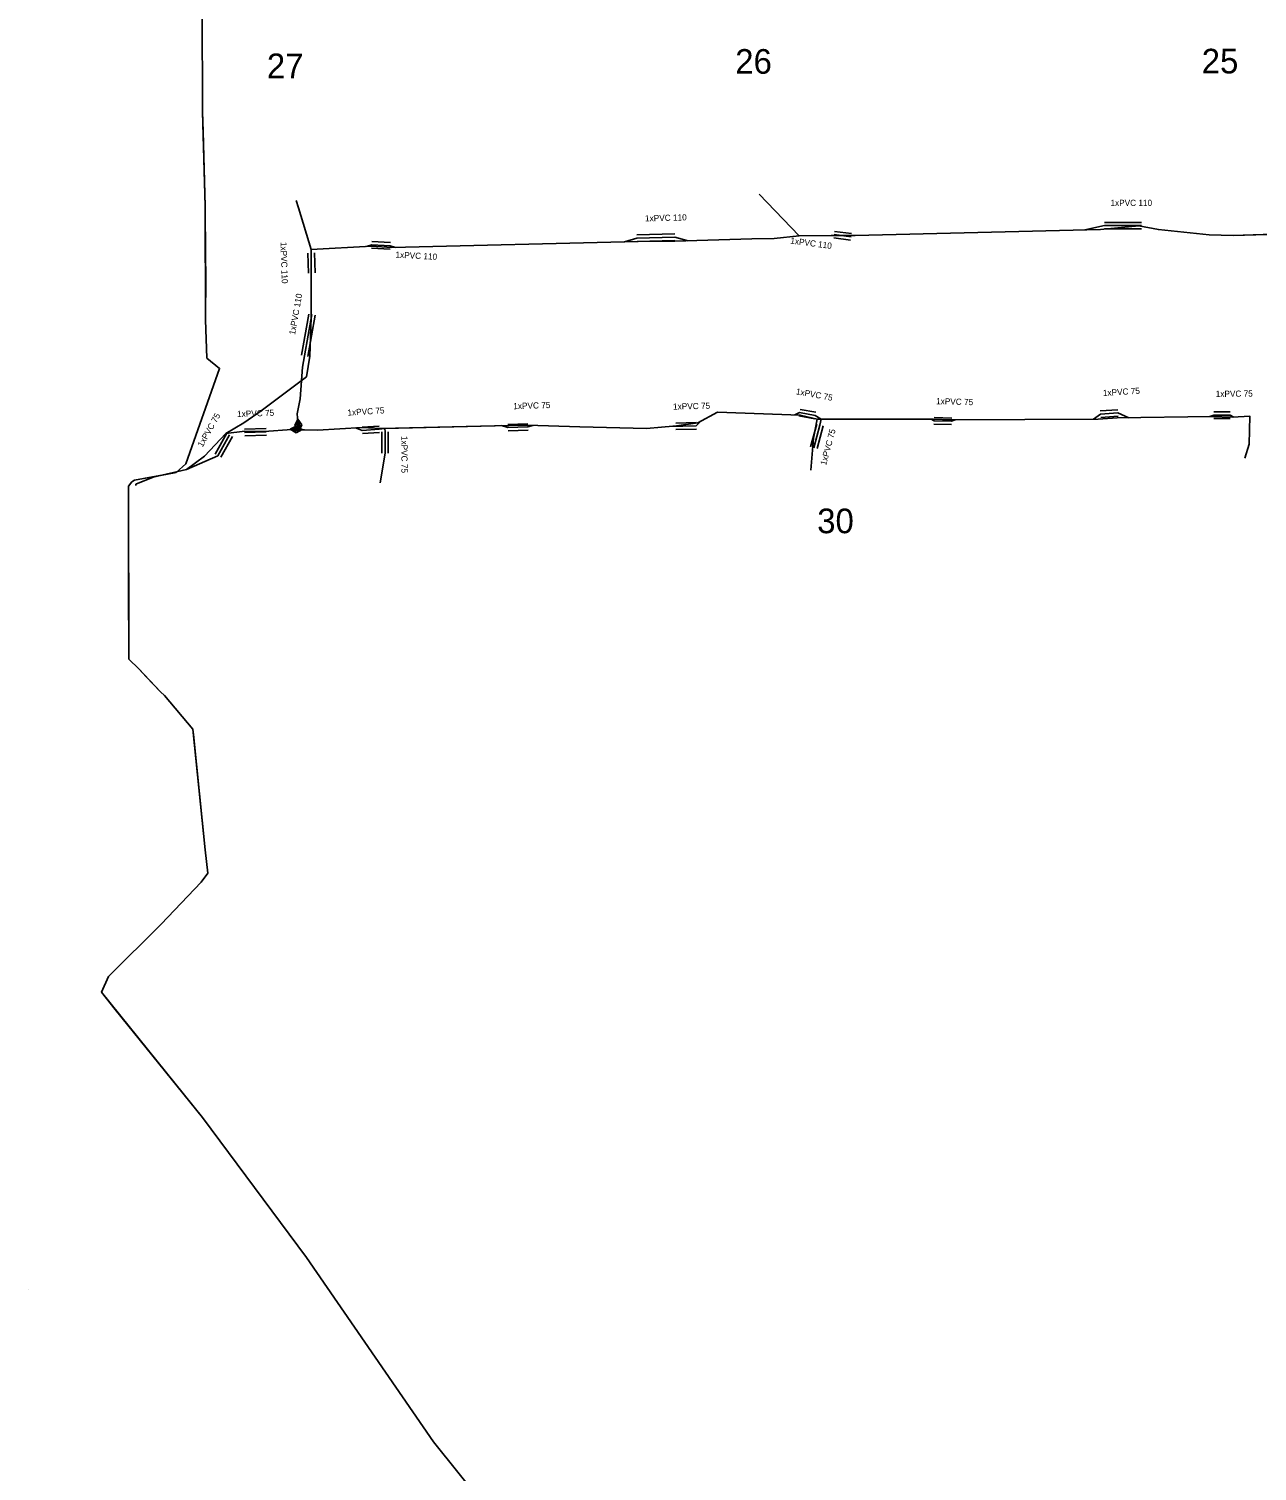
# Model space of a CAD drawing. Extents: x -651943 to -618711, y -1138561 to -1100552.
# Drawn here: x -641572.3 to -641422.8, y -1115022.1 to -1114846.4 of the extents above; entities that cross this region are included whole.
import ezdxf

# ---------------------------------------------------------------- set-up
doc = ezdxf.new("R2010")
doc.units = 0
for name, color, linetype in [('KT optika', 7, 'Continuous'), ('KT trasa', 7, 'Continuous'), ('KT zařízení', 7, 'Continuous'), ('SATT bloky', 7, 'Continuous'), ('SATT stanice', 7, 'Continuous')]:
    doc.layers.add(name, color=color, linetype=linetype)

# ---------------------------------------------------------------- blocks, each defined once
blk = doc.blocks.new('POINT_DISPLAY')
blk.add_line((0, 0), (0, 0))
blk = doc.blocks.new('TVSPO_1')
at = {"layer": 'KT zařízení'}
for p, q in [((-0.074, 0.002), (0, 0.044)), ((-0.001, -0.041), (-0.074, 0.002)), ((-0.035, 0), (0, 0.02)), ((0.073, 0.001), (-0.001, -0.041)), ((0, 0.044), (0.073, 0.001)), ((0, 0.02), (0.035, 0)), ((0.035, 0), (0, -0.02)), ((0, -0.02), (-0.035, 0))]:
    blk.add_line(p, q, dxfattribs=at)

msp = doc.modelspace()

# ---------------------------------------------------------------- linework, layer by layer
at = {"layer": 'KT optika'}
for points in [[(-641551.21, -1114844.02), (-641551.16, -1114856.5), (-641550.86, -1114868.02), (-641550.82, -1114881.85), (-641550.66, -1114886.51), (-641549.1, -1114887.77), (-641553.22, -1114899.39), (-641554.4, -1114900.46), (-641557.15, -1114900.97)], [(-641478.52, -1114871.61), (-641478.52, -1114871.61), (-641483.41, -1114866.54)], [(-641537.95, -1114873.29), (-641539.48, -1114868.22), (-641539.75, -1114867.3)], [(-641537.95, -1114873.29), (-641530.6, -1114872.9), (-641528.11, -1114873.06), (-641498.14, -1114872.31), (-641493.68, -1114872.28), (-641484.29, -1114871.98), (-641481.55, -1114871.94), (-641478.52, -1114871.61)], [(-641478.52, -1114871.61), (-641474.62, -1114871.59), (-641471.72, -1114871.6), (-641441.85, -1114870.85), (-641437.18, -1114870.41), (-641434.79, -1114870.87), (-641428.62, -1114871.49), (-641425.7, -1114871.59), (-641418.41, -1114871.36)], [(-641537.95, -1114873.29), (-641537.93, -1114879.08), (-641537.93, -1114881.58), (-641538.12, -1114886.28), (-641538.53, -1114888.79), (-641544.03, -1114892.94), (-641546.16, -1114894.4), (-641548.32, -1114895.69)], [(-641539.47, -1114895.24), (-641539.47, -1114895.24), (-641539.64, -1114893.32), (-641539.29, -1114891.49), (-641539, -1114887.63), (-641538.74, -1114886.24), (-641537.85, -1114881.22)], [(-641528.96, -1114895.08), (-641513.86, -1114894.72), (-641511.59, -1114894.69), (-641505.25, -1114894.88), (-641497.11, -1114895.09), (-641493.47, -1114894.78), (-641490.86, -1114894.4), (-641488.47, -1114893.09), (-641478.39, -1114893.45), (-641476.35, -1114893.94)], [(-641539.47, -1114895.24), (-641537.16, -1114895.31), (-641531.72, -1114894.98), (-641529.4, -1114895.09), (-641528.96, -1114895.08)], [(-641476.35, -1114893.94), (-641476.35, -1114893.94), (-641476.79, -1114896.27), (-641477.09, -1114900.15)], [(-641476.35, -1114893.94), (-641462.16, -1114893.97), (-641459.98, -1114894.05), (-641442.12, -1114893.94), (-641439.82, -1114893.8), (-641428.31, -1114893.64), (-641425.78, -1114893.7), (-641423.65, -1114893.61), (-641423.73, -1114897.02), (-641424.25, -1114898.7)], [(-641548.32, -1114895.69), (-641548.32, -1114895.69), (-641550.94, -1114898.46), (-641553.11, -1114900.1), (-641557.19, -1114901.02)], [(-641548.32, -1114895.69), (-641546.03, -1114895.41), (-641543.65, -1114895.44), (-641540.28, -1114895.22), (-641539.47, -1114895.24)], [(-641528.96, -1114895.08), (-641528.95, -1114895.49), (-641528.95, -1114898.1), (-641529.53, -1114901.7)], [(-641557.26, -1114900.99), (-641559.44, -1114901.39), (-641559.79, -1114901.6), (-641560.19, -1114902.13), (-641560.15, -1114923.19), (-641558.93, -1114924.36), (-641556.3, -1114927.18), (-641555.82, -1114927.61), (-641552.35, -1114931.72), (-641550.85, -1114946.43), (-641550.52, -1114949.25), (-641551.32, -1114950.36), (-641556.21, -1114955.48), (-641562.63, -1114961.85), (-641563.46, -1114963.76), (-641551.19, -1114979.03), (-641538.52, -1114996.06), (-641523.04, -1115018.52), (-641502.48, -1115044.21)]]:
    msp.add_lwpolyline(points, dxfattribs=at)
at = {"layer": 'KT trasa'}
for p, q in [((-641551.21, -1114844.02), (-641551.16, -1114856.5)), ((-641551.16, -1114856.5), (-641551.11, -1114858.93)), ((-641551.11, -1114858.93), (-641550.86, -1114868.02)), ((-641478.52, -1114871.61), (-641483.41, -1114866.54)), ((-641550.86, -1114868.02), (-641550.79, -1114874.2)), ((-641539.48, -1114868.22), (-641539.75, -1114867.3)), ((-641537.95, -1114873.29), (-641539.48, -1114868.22)), ((-641441.33, -1114870.38), (-641443.76, -1114870.9)), ((-641436.86, -1114870.38), (-641441.33, -1114870.38)), ((-641498.27, -1114871.9), (-641499.78, -1114872.35)), ((-641493.66, -1114871.78), (-641498.27, -1114871.9)), ((-641484.29, -1114871.98), (-641493.68, -1114872.28)), ((-641493.66, -1114871.78), (-641492.04, -1114872.23)), ((-641481.55, -1114871.94), (-641484.29, -1114871.98)), ((-641478.52, -1114871.61), (-641481.55, -1114871.94)), ((-641474.62, -1114871.59), (-641478.52, -1114871.61)), ((-641471.72, -1114871.6), (-641474.62, -1114871.59)), ((-641472.21, -1114871.75), (-641474.26, -1114871.48)), ((-641441.85, -1114870.85), (-641471.72, -1114871.6)), ((-641437.18, -1114870.41), (-641441.85, -1114870.85)), ((-641434.79, -1114870.87), (-641437.18, -1114870.41)), ((-641428.62, -1114871.49), (-641434.79, -1114870.87)), ((-641425.7, -1114871.59), (-641428.62, -1114871.49)), ((-641418.41, -1114871.36), (-641425.7, -1114871.59)), ((-641530.6, -1114872.9), (-641537.95, -1114873.29)), ((-641537.95, -1114873.29), (-641537.93, -1114879.08)), ((-641530.56, -1114872.71), (-641531.2, -1114872.93)), ((-641528.11, -1114873.06), (-641530.6, -1114872.9)), ((-641528.32, -1114872.83), (-641530.56, -1114872.71)), ((-641528.32, -1114872.83), (-641527.68, -1114873.05)), ((-641498.14, -1114872.31), (-641528.11, -1114873.06)), ((-641493.68, -1114872.28), (-641498.14, -1114872.31)), ((-641550.79, -1114874.2), (-641550.78, -1114876.49)), ((-641550.78, -1114876.49), (-641550.82, -1114881.85)), ((-641537.93, -1114879.08), (-641537.93, -1114881.58)), ((-641550.82, -1114881.85), (-641550.66, -1114886.51)), ((-641537.93, -1114881.58), (-641538.12, -1114886.28)), ((-641553.22, -1114899.39), (-641549.1, -1114887.77)), ((-641550.66, -1114886.51), (-641549.1, -1114887.77)), ((-641539, -1114887.63), (-641539.29, -1114891.49)), ((-641538.74, -1114886.24), (-641539, -1114887.63)), ((-641538.12, -1114886.28), (-641538.53, -1114888.79)), ((-641538.53, -1114888.79), (-641544.03, -1114892.94)), ((-641539.29, -1114891.49), (-641539.64, -1114893.32)), ((-641544.03, -1114892.94), (-641546.16, -1114894.4)), ((-641490.86, -1114894.4), (-641488.47, -1114893.09)), ((-641488.47, -1114893.09), (-641478.39, -1114893.45)), ((-641478.48, -1114893.16), (-641479.06, -1114893.42)), ((-641478.48, -1114893.16), (-641476.56, -1114893.51)), ((-641439.71, -1114893.2), (-641441.83, -1114893.34)), ((-641438.37, -1114893.78), (-641439.71, -1114893.2)), ((-641546.16, -1114894.4), (-641548.32, -1114895.69)), ((-641539.64, -1114893.32), (-641539.47, -1114895.24)), ((-641537.16, -1114895.31), (-641531.72, -1114894.98)), ((-641531.72, -1114894.98), (-641529.4, -1114895.09)), ((-641529.4, -1114895.09), (-641513.86, -1114894.72)), ((-641513.98, -1114894.99), (-641514.75, -1114894.74)), ((-641513.98, -1114894.99), (-641511.55, -1114894.91)), ((-641513.86, -1114894.72), (-641511.59, -1114894.69)), ((-641511.59, -1114894.69), (-641505.25, -1114894.88)), ((-641511.55, -1114894.91), (-641510.95, -1114894.71)), ((-641505.25, -1114894.88), (-641497.11, -1114895.09)), ((-641497.11, -1114895.09), (-641493.47, -1114894.78)), ((-641494.29, -1114894.85), (-641491.05, -1114894.77)), ((-641493.47, -1114894.78), (-641490.86, -1114894.4)), ((-641491.05, -1114894.77), (-641490.46, -1114894.18)), ((-641478.39, -1114893.45), (-641476.35, -1114893.94)), ((-641476.35, -1114893.94), (-641476.79, -1114896.27)), ((-641476, -1114894.67), (-641476.74, -1114897.44)), ((-641476.56, -1114893.51), (-641475.85, -1114893.94)), ((-641476.35, -1114893.94), (-641462.16, -1114893.97)), ((-641476, -1114894.67), (-641475.85, -1114893.94)), ((-641462.1, -1114894.16), (-641462.46, -1114893.97)), ((-641462.16, -1114893.97), (-641459.98, -1114894.05)), ((-641462.1, -1114894.16), (-641459.96, -1114894.22)), ((-641459.98, -1114894.05), (-641442.12, -1114893.94)), ((-641459.96, -1114894.22), (-641459.51, -1114894.04)), ((-641441.83, -1114893.34), (-641442.7, -1114893.95)), ((-641442.12, -1114893.94), (-641439.82, -1114893.8)), ((-641439.82, -1114893.8), (-641428.31, -1114893.64)), ((-641428.05, -1114893.48), (-641428.52, -1114893.64)), ((-641428.31, -1114893.64), (-641425.78, -1114893.7)), ((-641426.06, -1114893.46), (-641428.05, -1114893.48)), ((-641426.06, -1114893.46), (-641425.61, -1114893.7)), ((-641425.78, -1114893.7), (-641423.65, -1114893.61)), ((-641423.65, -1114893.61), (-641423.73, -1114897.02)), ((-641548.32, -1114895.69), (-641550.94, -1114898.46)), ((-641549.3, -1114898.41), (-641547.87, -1114895.86)), ((-641548.32, -1114895.69), (-641546.03, -1114895.41)), ((-641546.05, -1114895.58), (-641543.41, -1114895.49)), ((-641546.03, -1114895.41), (-641543.65, -1114895.44)), ((-641543.65, -1114895.44), (-641540.28, -1114895.22)), ((-641540.28, -1114895.22), (-641537.16, -1114895.31)), ((-641531.72, -1114895.32), (-641532.53, -1114895.03)), ((-641531.72, -1114895.32), (-641529.65, -1114895.19)), ((-641529.65, -1114895.19), (-641528.96, -1114895.08)), ((-641528.95, -1114895.49), (-641528.96, -1114895.08)), ((-641528.95, -1114895.49), (-641528.95, -1114898.1)), ((-641476.79, -1114896.27), (-641477.09, -1114900.15)), ((-641549.3, -1114898.41), (-641553.11, -1114900.1)), ((-641550.94, -1114898.46), (-641553.11, -1114900.1)), ((-641528.95, -1114898.1), (-641529.53, -1114901.7)), ((-641423.73, -1114897.02), (-641424.25, -1114898.7)), ((-641553.11, -1114900.1), (-641557.19, -1114901.02)), ((-641554.4, -1114900.46), (-641553.22, -1114899.39)), ((-641557.19, -1114901.02), (-641559.3, -1114901.88)), ((-641559.3, -1114901.88), (-641559.28, -1114902.05))]:
    msp.add_line(p, q, dxfattribs=at)
for points in [[(-641538.74, -1114886.24), (-641537.85, -1114881.22)], [(-641502.48, -1115044.21), (-641523.04, -1115018.52), (-641538.52, -1114996.06), (-641551.19, -1114979.03), (-641561.81, -1114965.88), (-641563.46, -1114963.76), (-641562.63, -1114961.85), (-641556.21, -1114955.48), (-641551.32, -1114950.36), (-641550.52, -1114949.25), (-641550.85, -1114946.43), (-641552.29, -1114932.38), (-641552.35, -1114931.72), (-641555.82, -1114927.61), (-641556.3, -1114927.18), (-641558.02, -1114925.33), (-641558.93, -1114924.36), (-641560.15, -1114923.19), (-641560.18, -1114913.79), (-641560.19, -1114902.13), (-641559.79, -1114901.6), (-641559.44, -1114901.39), (-641554.4, -1114900.46)]]:
    msp.add_lwpolyline(points, dxfattribs=at)
at = {"layer": 'KT zařízení'}
for p, q in [((-641436.86, -1114869.98), (-641441.33, -1114869.98)), ((-641493.67, -1114871.38), (-641498.28, -1114871.5)), ((-641472.26, -1114872.15), (-641474.31, -1114871.88)), ((-641472.16, -1114871.35), (-641474.21, -1114871.08)), ((-641436.86, -1114870.78), (-641441.33, -1114870.78)), ((-641538.34, -1114873.72), (-641538.26, -1114876.17)), ((-641537.54, -1114873.7), (-641537.46, -1114876.15)), ((-641528.34, -1114873.23), (-641530.58, -1114873.11)), ((-641528.3, -1114872.43), (-641530.54, -1114872.31)), ((-641493.65, -1114872.18), (-641498.26, -1114872.3)), ((-641538.24, -1114881.15), (-641539.13, -1114886.17)), ((-641537.46, -1114881.29), (-641538.35, -1114886.31)), ((-641478.41, -1114892.77), (-641476.49, -1114893.12)), ((-641439.74, -1114892.8), (-641441.86, -1114892.94)), ((-641426.06, -1114893.06), (-641428.05, -1114893.08)), ((-641531.74, -1114894.92), (-641529.68, -1114894.79)), ((-641513.99, -1114894.59), (-641511.56, -1114894.51)), ((-641493.56, -1114894.43), (-641491.06, -1114894.37)), ((-641478.55, -1114893.55), (-641476.63, -1114893.9)), ((-641476.39, -1114894.57), (-641477.13, -1114897.34)), ((-641475.61, -1114894.77), (-641476.35, -1114897.54)), ((-641462.11, -1114894.56), (-641459.97, -1114894.62)), ((-641462.09, -1114893.76), (-641459.95, -1114893.82)), ((-641439.68, -1114893.6), (-641441.8, -1114893.74)), ((-641426.06, -1114893.86), (-641428.05, -1114893.88)), ((-641549.65, -1114898.21), (-641548.22, -1114895.66)), ((-641548.95, -1114898.6), (-641547.52, -1114896.06)), ((-641546.06, -1114895.18), (-641543.42, -1114895.09)), ((-641546.04, -1114895.98), (-641543.4, -1114895.89)), ((-641531.69, -1114895.72), (-641529.62, -1114895.59)), ((-641529.35, -1114895.49), (-641529.35, -1114898.1)), ((-641528.55, -1114895.49), (-641528.55, -1114898.1)), ((-641513.97, -1114895.39), (-641511.54, -1114895.31)), ((-641493.54, -1114895.23), (-641491.04, -1114895.17))]:
    msp.add_line(p, q, dxfattribs=at)

# ---------------------------------------------------------------- block references
at = {"layer": 'KT zařízení', "yscale": 10.000012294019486}
for p, xscale, rotation in [((-641539.77, -1114895.23), 10.000012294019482, -1.2378374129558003), ((-641539.52, -1114894.68), 10.000012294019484, -83.97917855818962)]:
    msp.add_blockref('TVSPO_1', p, dxfattribs=dict(at, xscale=xscale, rotation=rotation))
at = {"layer": 'SATT stanice'}
msp.add_blockref('POINT_DISPLAY', (-641572.32, -1114999.96), dxfattribs=at)

# ---------------------------------------------------------------- texts
at = {"layer": 'KT zařízení'}
msp.add_text('1xPVC 110', height=0.75, dxfattribs=at).set_placement((-641440.62, -1114867.98))
for s, rotation, p in [('1xPVC 110', 1.4911, (-641497.28, -1114869.87)), ('1xPVC 110', 352.4969, (-641479.63, -1114872.56)), ('1xPVC 110', 271.8702, (-641541.68, -1114872.38)), ('1xPVC 110', 356.9335, (-641527.69, -1114874.28)), ('1xPVC 110', 79.9465, (-641539.91, -1114883.72)), ('1xPVC 75', 349.6689, (-641478.96, -1114890.92)), ('1xPVC 75', 358.394, (-641461.86, -1114892.13)), ('1xPVC 75', 3.7782, (-641441.52, -1114891.15)), ('1xPVC 75', 0.5758, (-641427.8, -1114891.25)), ('1xPVC 75', 60.717, (-641551.17, -1114897.43)), ('1xPVC 75', 1.9525, (-641546.95, -1114893.7)), ('1xPVC 75', 3.5936, (-641533.5, -1114893.53)), ('1xPVC 75', 1.8856, (-641513.32, -1114892.75)), ('1xPVC 75', 1.3748, (-641493.87, -1114892.8)), ('1xPVC 75', 270, (-641526.96, -1114896)), ('1xPVC 75', 75.0428, (-641475.24, -1114899.63))]:
    msp.add_text(s, height=0.75, rotation=rotation, dxfattribs=at).set_placement(p)
at = {"layer": 'SATT bloky'}
for s, p in [('26', (-641486.31, -1114851.88)), ('25', (-641429.51, -1114851.84)), ('27', (-641543.34, -1114852.42)), ('30', (-641476.33, -1114907.85))]:
    msp.add_text(s, height=3, dxfattribs=at).set_placement(p)

doc.saveas('drawing.dxf')
